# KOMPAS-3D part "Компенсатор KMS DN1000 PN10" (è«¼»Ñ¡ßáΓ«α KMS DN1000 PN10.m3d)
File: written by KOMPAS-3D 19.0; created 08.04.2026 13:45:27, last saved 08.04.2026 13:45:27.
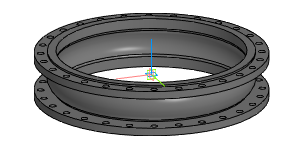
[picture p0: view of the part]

Document properties: Автор: Энергия; Полное имя файла: Z:\3.Личные\kachalov\3d для проектировщиков\7.1 Компенсатор\stp_Компенсатор KSM\Компенсатор KMS DN1000 PN10.m3d

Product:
- Part/product: Компенсатор KMS DN1000 PN10

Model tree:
1. Операция без истории:1  (labels: Компенсатор KMS DN1000 PN10)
